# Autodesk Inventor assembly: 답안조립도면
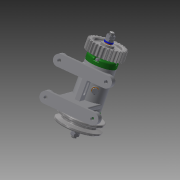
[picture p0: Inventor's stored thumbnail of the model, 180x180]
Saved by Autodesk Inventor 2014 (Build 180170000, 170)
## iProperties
Created: 2015-11
Part Number: 답안조립도면
Document SubType Name: Assembly
Designer: Owner
Author: Owner
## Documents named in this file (16)
- C:\Documents and Settings\Owner\바탕 화면\451109V1013\답안조립도면.iam
- C:\Documents and Settings\Owner\바탕 화면\451109V1013\부품1.ipt
- C:\Documents and Settings\Owner\바탕 화면\451109V1013\커버.ipt
- C:\Documents and Settings\Owner\바탕 화면\451109V1013\베어링 15 x 32 x 9.ipt
- C:\Documents and Settings\Owner\바탕 화면\451109V1013\오일 실 15 25 7.ipt
- C:\Documents and Settings\Owner\바탕 화면\451109V1013\축.ipt
- C:\Documents and Settings\Owner\바탕 화면\451109V1013\키 3 x 3 x 12.ipt
- C:\Documents and Settings\Owner\바탕 화면\451109V1013\니플 M 6 x 0.75.ipt
- C:\Documents and Settings\Owner\바탕 화면\451109V1013\볼트 M4 x 12.ipt
- C:\Documents and Settings\Owner\바탕 화면\451109V1013\V벨트풀리.ipt
- C:\Documents and Settings\Owner\바탕 화면\451109V1013\스퍼기어.ipt
- C:\Documents and Settings\Owner\바탕 화면\451109V1013\와셔 8x17.ipt
- C:\Documents and Settings\Owner\바탕 화면\451109V1013\스프링와셔 8.ipt
- C:\Documents and Settings\Owner\바탕 화면\451109V1013\너트 M 8.ipt
- C:\Documents and Settings\Owner\바탕 화면\451109V1013\와셔 6x11.5.ipt
- C:\Documents and Settings\Owner\바탕 화면\451109V1013\볼트 M 6 x 8.ipt
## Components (11 placed, 3 different names)
1. KS B 2023 6002 - 15 x 32 x 9:1
2. KS B 2023 6002 - 15 x 32 x 9:2
3. V벨트풀리:1
4. ISO 4762 M4 x 12:1
5. ISO 4762 M4 x 12:3
6. ISO 4762 M4 x 12:4
7. ISO 4762 M4 x 12:5
8. ISO 4762 M4 x 12:2
9. ISO 4762 M4 x 12:6
10. ISO 4762 M4 x 12:7
11. ISO 4762 M4 x 12:8
